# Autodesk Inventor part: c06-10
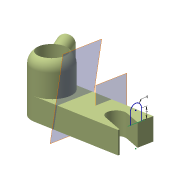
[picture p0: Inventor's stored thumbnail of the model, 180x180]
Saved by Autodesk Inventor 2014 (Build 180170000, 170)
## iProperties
Created: 2013-03
Part Number: c06-10
Material: Aluminum 6061
Document SubType Name: Modeling
Designer: Thom Tremblay
Density: 2.71 g/cm^3
Appearance: Zinc Chromate 2
Author: Thom Tremblay
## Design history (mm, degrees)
sketch "Sketch1"
  geometry: L1 (0, -12.5)-(60, -12.5); L2 (60, -12.5)-(60, 12.5); L3 (60, 12.5)-(0, 12.5); L4 (0, 12.5)-(0, -12.5); 2 further points
  constraints: 8 end point, 2 parallel, 1 coincident, 1 horizontal, 1 midpoint, 1 perpendicular
  dimensions: "d1" = 25 distance of L2.end L1.end; "d2" = 60 distance of L2.end L3.end
extrude "Base" new body sketch "Sketch1" distance "d3" = 14; taper "d4" = 0 deg
sketch "Sketch2"
  geometry: C1 r 12.5 at (0, 0); 1 further point
  constraints: 1 centre point, 1 coincident
extrude "Boss" join sketch "Sketch2" distance "d5" = 35; taper "d6" = 0 deg
sketch "Sketch3"
  geometry: L1 (-60, 12.5)-(-60, -12.5) reference; L2 (-60, -6)-(-60, 6); L3 (-43.948, 5.638)-(-60, 11.481); L4 (-48.052, -5.638)-(-60, -1.289); L5 (-60, 11.481)-(-60, -1.289); A1 r 6 centre (-46, 0) between (-43.948, 5.638) and (-48.052, -5.638); 2 further points
  constraints: 8 end point, 3 midpoint, 2 point on circle, 2 point on line, 2 tangent, 1 centre point, 1 collinear, 1 horizontal alignment, 1 parallel
  dimensions: "d8" = 12 diameter of A1; "d20" = 20 dimension on A1 L1; "d27" = 70 deg angle of L1 L3
extrude "Slot" cut sketch "Sketch3" stored distance "d9" = 24; taper "d10" = 0 deg
hole "Hole1" diameter "d13" = 11; stored, may be unused: countersink angle "d17" = 90 deg, drill point angle "d19" = 118 deg; dims "d11" = 10, "d12" = 10, "d14" = 6, "d15" = 18, "d16" = 11, "d18" = 8
fillet "Fillet1" dims "d26" = 8
node "Midplane between faces"
node "Normal to Edge at Point"
node "Offset Plane"
  node "Tangent Plane"
sketch "Sketch4"
  geometry: L1 (0, 0)-(-60, 0) reference; L2 (-14, 0)-(-18.341, 24.62)
  constraints: 2 end point, 1 point on line
  dimensions: "d21" = 25 distance of L2.start L2.end; "d22" = 80 deg angle of L1 L2; "d23" = 14 distance of L1.start L2.start
node "Plane at Angle on Sketch"
sketch "Sketch5"
  geometry: L1 (0, 0)-(-19.151, 16.07); L2 (0, 0)-(25, 0); C1 r 9 at (0, 0) reference; C2 r 5.5 at (0, 0) reference
  constraints: 4 end point, 1 equal length, 1 horizontal
  dimensions: "d24" = 25 distance of L1.start L1.end; "d25" = 140 deg angle of L2 L1
node "Plane using Sketch as Axis"
sketch "Sketch6"
  geometry: L1 (33, 0)-(8, 0); L2 (28, -5)-(13, -5); L3 (13, 5)-(28, 5); L4 (35, 9)-(35, -9) reference; A1 r 5 centre (28, 0) between (28, -5) and (28, 5); A2 r 5 centre (13, 0) between (13, 5) and (13, -5); 2 further points
  constraints: 8 end point, 6 point on circle, 4 tangent, 3 point on line, 2 centre point, 1 horizontal, 1 midpoint, 1 parallel
  dimensions: "d33" = 2 distance from line of L1.start L4; "d34" = 25 distance of L1.start L1.end; "d35" = 5 radius of A2
extrude "Extrusion4" join sketch "Sketch6" stored distance "d37" = 10; taper "d38" = 0 deg
sketch "Sketch7"
  geometry: L1 (-18.138, 14)-(-6.5, 14) reference; L2 (-16.5, 14)-(-16.5, 21); L3 (-8.5, 21)-(-8.5, 14); A1 r 4 centre (-12.5, 21) between (-8.5, 21) and (-16.5, 21); 2 further points
  constraints: 4 end point, 2 perpendicular, 2 point on circle, 2 point on line, 2 tangent, 1 centre point, 1 vertical alignment
  dimensions: "d31" = 7 distance of L3.start L3.end; "d32" = 4 radius of A1
sketch "Sketch8"
  geometry: L1 (0, 9)-(0, -9) reference; C1 r 3.5 at (0, 0); 1 further point
  constraints: 1 centre point, 1 midpoint
  dimensions: "d36" = 7 diameter of C1
body "Solid1"
workaxis "Work Axis1"
node "Plane at Angle"
other parameters: "d28" = 30 deg, "d29" = 15, "d30" = 90 deg
